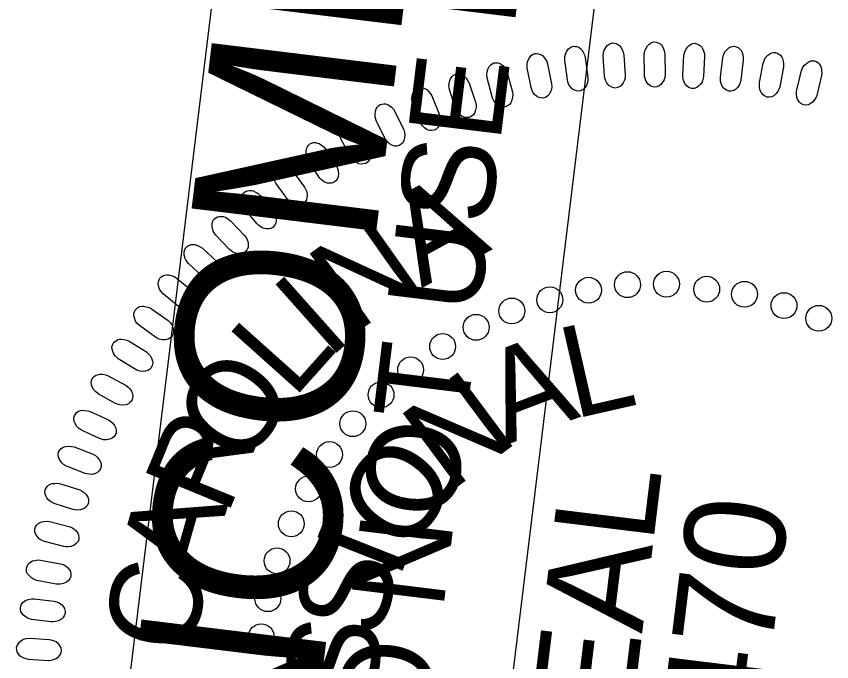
# Model space of a CAD drawing. Extents: x 480792 to 482083, y 490046 to 491850.
# Drawn here: x 481060.3 to 481110.8, y 491670.1 to 491710 of the extents above; entities that cross this region are included whole.
import ezdxf

# ---------------------------------------------------------------- set-up
doc = ezdxf.new("R2010")
doc.units = 0
doc.layers.add('Sheet PE Seal Cell', color=7, linetype='Continuous')
doc.layers.add('Sheet Sticker Incomplete CELL', color=7, linetype='Continuous')

msp = doc.modelspace()

# ---------------------------------------------------------------- linework, layer by layer
at = {"layer": 'Sheet PE Seal Cell'}
for points in [[(481096.688, 491706.346), (481096.606, 491707.57), (481096.629, 491707.792), (481096.671, 491707.935), (481096.772, 491708.111), (481096.862, 491708.227), (481096.969, 491708.315), (481097.07, 491708.361), (481097.181, 491708.389), (481097.294, 491708.376), (481097.416, 491708.353), (481097.523, 491708.301), (481097.634, 491708.209), (481097.7, 491708.133), (481097.777, 491707.988), (481097.848, 491707.813), (481097.881, 491707.656), (481097.973, 491706.402), (481097.961, 491706.231), (481097.926, 491706.089), (481097.847, 491705.924), (481097.744, 491705.777), (481097.653, 491705.691), (481097.5, 491705.621), (481097.352, 491705.591), (481097.201, 491705.621), (481097.093, 491705.664), (481096.959, 491705.755), (481096.829, 491705.916), (481096.749, 491706.091), (481096.711, 491706.218)], [(481099.157, 491706.446), (481099.153, 491707.672), (481099.189, 491707.892), (481099.241, 491708.032), (481099.352, 491708.202), (481099.449, 491708.312), (481099.561, 491708.392), (481099.665, 491708.433), (481099.777, 491708.453), (481099.889, 491708.433), (481100.009, 491708.404), (481100.115, 491708.345), (481100.219, 491708.245), (481100.279, 491708.166), (481100.347, 491708.016), (481100.408, 491707.837), (481100.431, 491707.677), (481100.443, 491706.421), (481100.421, 491706.251), (481100.377, 491706.111), (481100.288, 491705.952), (481100.176, 491705.811), (481100.079, 491705.731), (481099.923, 491705.67), (481099.773, 491705.65), (481099.623, 491705.69), (481099.519, 491705.739), (481099.391, 491705.838), (481099.271, 491706.007), (481099.203, 491706.187), (481099.173, 491706.317)], [(481101.534, 491706.401), (481101.607, 491707.625), (481101.657, 491707.842), (481101.717, 491707.978), (481101.839, 491708.141), (481101.942, 491708.245), (481102.06, 491708.318), (481102.166, 491708.351), (481102.279, 491708.365), (481102.39, 491708.338), (481102.508, 491708.301), (481102.608, 491708.236), (481102.707, 491708.13), (481102.762, 491708.046), (481102.821, 491707.893), (481102.87, 491707.71), (481102.883, 491707.55), (481102.816, 491706.295), (481102.783, 491706.127), (481102.73, 491705.99), (481102.631, 491705.836), (481102.511, 491705.704), (481102.41, 491705.63), (481102.249, 491705.579), (481102.099, 491705.568), (481101.952, 491705.617), (481101.85, 491705.673), (481101.729, 491705.78), (481101.62, 491705.956), (481101.563, 491706.139), (481101.541, 491706.27)], [(481092.141, 491705.638), (481091.906, 491706.842), (481091.901, 491707.065), (481091.926, 491707.212), (481092.004, 491707.399), (481092.078, 491707.526), (481092.173, 491707.626), (481092.267, 491707.685), (481092.374, 491707.725), (481092.488, 491707.727), (481092.611, 491707.721), (481092.725, 491707.682), (481092.847, 491707.604), (481092.921, 491707.538), (481093.016, 491707.403), (481093.109, 491707.239), (481093.162, 491707.086), (481093.409, 491705.854), (481093.419, 491705.684), (481093.401, 491705.538), (481093.344, 491705.365), (481093.261, 491705.206), (481093.18, 491705.109), (481093.038, 491705.02), (481092.895, 491704.972), (481092.74, 491704.983), (481092.629, 491705.012), (481092.484, 491705.085), (481092.335, 491705.228), (481092.234, 491705.392), (481092.18, 491705.514)], [(481094.388, 491706.114), (481094.23, 491707.33), (481094.239, 491707.552), (481094.272, 491707.698), (481094.362, 491707.881), (481094.444, 491708.002), (481094.545, 491708.095), (481094.643, 491708.148), (481094.752, 491708.182), (481094.866, 491708.178), (481094.989, 491708.163), (481095.099, 491708.118), (481095.216, 491708.032), (481095.286, 491707.961), (481095.372, 491707.821), (481095.455, 491707.65), (481095.498, 491707.495), (481095.667, 491706.25), (481095.667, 491706.079), (481095.64, 491705.935), (481095.572, 491705.765), (481095.479, 491705.612), (481095.393, 491705.52), (481095.245, 491705.441), (481095.099, 491705.402), (481094.946, 491705.422), (481094.836, 491705.458), (481094.697, 491705.54), (481094.556, 491705.693), (481094.466, 491705.862), (481094.42, 491705.987)], [(481103.865, 491706.266), (481104.015, 491707.484), (481104.078, 491707.697), (481104.147, 491707.829), (481104.279, 491707.984), (481104.389, 491708.082), (481104.51, 491708.147), (481104.618, 491708.173), (481104.732, 491708.179), (481104.841, 491708.146), (481104.956, 491708.102), (481105.053, 491708.03), (481105.144, 491707.918), (481105.194, 491707.832), (481105.243, 491707.675), (481105.28, 491707.49), (481105.283, 491707.329), (481105.138, 491706.08), (481105.095, 491705.915), (481105.033, 491705.782), (481104.925, 491705.634), (481104.797, 491705.509), (481104.691, 491705.442), (481104.527, 491705.401), (481104.377, 491705.4), (481104.233, 491705.458), (481104.136, 491705.52), (481104.021, 491705.634), (481103.924, 491705.817), (481103.878, 491706.004), (481103.864, 491706.136)], [(481106.284, 491705.938), (481106.509, 491707.144), (481106.586, 491707.352), (481106.663, 491707.48), (481106.805, 491707.626), (481106.92, 491707.716), (481107.045, 491707.774), (481107.155, 491707.794), (481107.27, 491707.793), (481107.375, 491707.752), (481107.488, 491707.701), (481107.58, 491707.623), (481107.664, 491707.506), (481107.708, 491707.417), (481107.747, 491707.257), (481107.773, 491707.069), (481107.766, 491706.908), (481107.542, 491705.672), (481107.489, 491705.51), (481107.419, 491705.381), (481107.302, 491705.24), (481107.166, 491705.124), (481107.056, 491705.063), (481106.89, 491705.033), (481106.739, 491705.041), (481106.6, 491705.108), (481106.506, 491705.176), (481106.4, 491705.297), (481106.313, 491705.485), (481106.28, 491705.675), (481106.275, 491705.807)], [(481108.586, 491705.488), (481108.887, 491706.678), (481108.977, 491706.881), (481109.061, 491707.004), (481109.212, 491707.142), (481109.333, 491707.224), (481109.461, 491707.273), (481109.572, 491707.287), (481109.686, 491707.278), (481109.79, 491707.232), (481109.899, 491707.173), (481109.985, 491707.09), (481110.062, 491706.967), (481110.101, 491706.876), (481110.129, 491706.714), (481110.143, 491706.525), (481110.126, 491706.365), (481109.825, 491705.145), (481109.762, 491704.985), (481109.684, 491704.861), (481109.558, 491704.729), (481109.415, 491704.621), (481109.302, 491704.567), (481109.135, 491704.548), (481108.985, 491704.565), (481108.85, 491704.641), (481108.76, 491704.714), (481108.661, 491704.842), (481108.588, 491705.036), (481108.566, 491705.227), (481108.569, 491705.359)], [(481089.738, 491705.051), (481089.428, 491706.238), (481089.409, 491706.459), (481089.424, 491706.608), (481089.49, 491706.8), (481089.557, 491706.931), (481089.645, 491707.036), (481089.736, 491707.101), (481089.84, 491707.149), (481089.953, 491707.157), (481090.076, 491707.159), (481090.192, 491707.128), (481090.319, 491707.057), (481090.397, 491706.996), (481090.5, 491706.868), (481090.603, 491706.709), (481090.665, 491706.56), (481090.989, 491705.346), (481091.011, 491705.177), (481091.002, 491705.03), (481090.956, 491704.853), (481090.883, 491704.69), (481090.809, 491704.588), (481090.672, 491704.49), (481090.532, 491704.433), (481090.378, 491704.434), (481090.264, 491704.456), (481090.115, 491704.52), (481089.957, 491704.655), (481089.846, 491704.811), (481089.785, 491704.929)], [(481087.474, 491704.341), (481087.09, 491705.506), (481087.057, 491705.726), (481087.063, 491705.875), (481087.117, 491706.071), (481087.175, 491706.205), (481087.256, 491706.317), (481087.343, 491706.387), (481087.444, 491706.441), (481087.556, 491706.457), (481087.679, 491706.466), (481087.797, 491706.442), (481087.928, 491706.38), (481088.01, 491706.323), (481088.121, 491706.201), (481088.233, 491706.05), (481088.304, 491705.905), (481088.704, 491704.714), (481088.736, 491704.546), (481088.737, 491704.399), (481088.702, 491704.22), (481088.639, 491704.052), (481088.572, 491703.946), (481088.441, 491703.84), (481088.305, 491703.774), (481088.151, 491703.765), (481088.036, 491703.78), (481087.884, 491703.835), (481087.717, 491703.959), (481087.597, 491704.108), (481087.529, 491704.222)], [(481085.272, 491703.494), (481084.816, 491704.633), (481084.77, 491704.85), (481084.765, 491704.999), (481084.806, 491705.198), (481084.856, 491705.336), (481084.931, 491705.452), (481085.014, 491705.528), (481085.11, 491705.588), (481085.221, 491705.611), (481085.343, 491705.628), (481085.463, 491705.612), (481085.597, 491705.558), (481085.682, 491705.506), (481085.8, 491705.392), (481085.922, 491705.247), (481086.003, 491705.108), (481086.477, 491703.944), (481086.519, 491703.778), (481086.529, 491703.631), (481086.505, 491703.45), (481086.453, 491703.28), (481086.392, 491703.169), (481086.269, 491703.055), (481086.137, 491702.981), (481085.984, 491702.962), (481085.868, 491702.969), (481085.713, 491703.015), (481085.539, 491703.128), (481085.41, 491703.27), (481085.334, 491703.379)], [(481083.085, 491702.491), (481082.558, 491703.598), (481082.497, 491703.813), (481082.484, 491703.961), (481082.513, 491704.163), (481082.554, 491704.304), (481082.62, 491704.424), (481082.698, 491704.505), (481082.791, 491704.571), (481082.9, 491704.601), (481083.022, 491704.625), (481083.141, 491704.616), (481083.279, 491704.571), (481083.367, 491704.525), (481083.493, 491704.418), (481083.623, 491704.282), (481083.712, 491704.148), (481084.258, 491703.016), (481084.311, 491702.853), (481084.33, 491702.708), (481084.317, 491702.525), (481084.276, 491702.35), (481084.223, 491702.237), (481084.107, 491702.115), (481083.98, 491702.033), (481083.828, 491702.005), (481083.712, 491702.005), (481083.554, 491702.041), (481083.374, 491702.142), (481083.236, 491702.276), (481083.153, 491702.38)], [(481080.983, 491701.336), (481080.388, 491702.409), (481080.314, 491702.619), (481080.292, 491702.766), (481080.308, 491702.97), (481080.34, 491703.112), (481080.399, 491703.236), (481080.471, 491703.322), (481080.56, 491703.394), (481080.668, 491703.431), (481080.786, 491703.463), (481080.907, 491703.461), (481081.047, 491703.425), (481081.138, 491703.384), (481081.269, 491703.285), (481081.409, 491703.158), (481081.506, 491703.029), (481082.122, 491701.934), (481082.184, 491701.775), (481082.213, 491701.63), (481082.212, 491701.448), (481082.181, 491701.271), (481082.135, 491701.154), (481082.027, 491701.026), (481081.906, 491700.936), (481081.756, 491700.898), (481081.64, 491700.891), (481081.48, 491700.917), (481081.294, 491701.007), (481081.148, 491701.131), (481081.059, 491701.231)], [(481078.997, 491700.108), (481078.335, 491701.141), (481078.249, 491701.346), (481078.217, 491701.492), (481078.221, 491701.695), (481078.243, 491701.84), (481078.295, 491701.968), (481078.361, 491702.058), (481078.445, 491702.135), (481078.55, 491702.179), (481078.667, 491702.218), (481078.788, 491702.224), (481078.93, 491702.196), (481079.023, 491702.161), (481079.16, 491702.071), (481079.307, 491701.952), (481079.412, 491701.83), (481080.096, 491700.776), (481080.168, 491700.621), (481080.206, 491700.479), (481080.216, 491700.296), (481080.197, 491700.118), (481080.158, 491699.998), (481080.059, 491699.863), (481079.943, 491699.766), (481079.796, 491699.719), (481079.681, 491699.705), (481079.52, 491699.72), (481079.328, 491699.799), (481079.174, 491699.914), (481079.079, 491700.007)], [(481077.068, 491698.719), (481076.343, 491699.709), (481076.244, 491699.908), (481076.203, 491700.052), (481076.193, 491700.255), (481076.207, 491700.4), (481076.25, 491700.531), (481076.311, 491700.626), (481076.39, 491700.708), (481076.492, 491700.758), (481076.607, 491700.805), (481076.726, 491700.818), (481076.87, 491700.8), (481076.965, 491700.77), (481077.108, 491700.689), (481077.262, 491700.58), (481077.375, 491700.465), (481078.123, 491699.455), (481078.205, 491699.305), (481078.251, 491699.166), (481078.273, 491698.984), (481078.265, 491698.805), (481078.234, 491698.683), (481078.143, 491698.542), (481078.034, 491698.438), (481077.89, 491698.381), (481077.776, 491698.36), (481077.614, 491698.365), (481077.418, 491698.432), (481077.257, 491698.537), (481077.157, 491698.624)], [(481075.176, 491697.193), (481074.39, 491698.136), (481074.278, 491698.328), (481074.229, 491698.469), (481074.206, 491698.671), (481074.211, 491698.817), (481074.246, 491698.95), (481074.3, 491699.048), (481074.374, 491699.135), (481074.473, 491699.192), (481074.584, 491699.245), (481074.702, 491699.266), (481074.847, 491699.257), (481074.944, 491699.234), (481075.091, 491699.162), (481075.252, 491699.062), (481075.372, 491698.954), (481076.182, 491697.994), (481076.273, 491697.849), (481076.328, 491697.713), (481076.361, 491697.533), (481076.365, 491697.355), (481076.341, 491697.23), (481076.259, 491697.084), (481076.157, 491696.973), (481076.017, 491696.908), (481075.904, 491696.879), (481075.743, 491696.875), (481075.542, 491696.928), (481075.376, 491697.023), (481075.27, 491697.104)], [(481073.458, 491695.618), (481072.615, 491696.509), (481072.491, 491696.694), (481072.433, 491696.831), (481072.398, 491697.032), (481072.393, 491697.178), (481072.42, 491697.313), (481072.468, 491697.414), (481072.537, 491697.506), (481072.631, 491697.568), (481072.739, 491697.629), (481072.856, 491697.657), (481073, 491697.657), (481073.099, 491697.64), (481073.25, 491697.577), (481073.417, 491697.488), (481073.543, 491697.388), (481074.412, 491696.48), (481074.513, 491696.342), (481074.576, 491696.209), (481074.62, 491696.032), (481074.635, 491695.853), (481074.62, 491695.728), (481074.547, 491695.577), (481074.451, 491695.46), (481074.315, 491695.386), (481074.205, 491695.35), (481074.044, 491695.336), (481073.841, 491695.377), (481073.668, 491695.461), (481073.558, 491695.535)], [(481071.822, 491693.909), (481070.925, 491694.746), (481070.79, 491694.923), (481070.723, 491695.056), (481070.676, 491695.254), (481070.662, 491695.399), (481070.679, 491695.536), (481070.722, 491695.64), (481070.784, 491695.736), (481070.875, 491695.804), (481070.978, 491695.871), (481071.093, 491695.907), (481071.238, 491695.915), (481071.337, 491695.905), (481071.492, 491695.852), (481071.664, 491695.773), (481071.796, 491695.681), (481072.721, 491694.83), (481072.829, 491694.697), (481072.901, 491694.569), (481072.957, 491694.395), (481072.983, 491694.218), (481072.974, 491694.092), (481072.911, 491693.937), (481072.823, 491693.814), (481072.693, 491693.731), (481072.585, 491693.689), (481072.425, 491693.664), (481072.22, 491693.692), (481072.042, 491693.766), (481071.927, 491693.832)], [(481070.316, 491692.079), (481069.368, 491692.857), (481069.222, 491693.025), (481069.148, 491693.154), (481069.087, 491693.348), (481069.064, 491693.493), (481069.074, 491693.63), (481069.109, 491693.736), (481069.165, 491693.836), (481069.252, 491693.91), (481069.351, 491693.983), (481069.463, 491694.026), (481069.607, 491694.044), (481069.706, 491694.039), (481069.865, 491693.997), (481070.042, 491693.929), (481070.179, 491693.845), (481071.155, 491693.053), (481071.272, 491692.928), (481071.351, 491692.805), (481071.418, 491692.635), (481071.455, 491692.46), (481071.455, 491692.334), (481071.401, 491692.174), (481071.322, 491692.046), (481071.196, 491691.956), (481071.091, 491691.907), (481070.933, 491691.871), (481070.727, 491691.887), (481070.545, 491691.949), (481070.426, 491692.008)], [(481068.89, 491690.18), (481067.895, 491690.896), (481067.739, 491691.055), (481067.656, 491691.179), (481067.585, 491691.369), (481067.552, 491691.512), (481067.553, 491691.65), (481067.582, 491691.758), (481067.631, 491691.861), (481067.713, 491691.94), (481067.807, 491692.019), (481067.917, 491692.07), (481068.059, 491692.096), (481068.159, 491692.098), (481068.319, 491692.066), (481068.5, 491692.008), (481068.643, 491691.934), (481069.666, 491691.205), (481069.791, 491691.088), (481069.878, 491690.97), (481069.955, 491690.804), (481070.003, 491690.631), (481070.011, 491690.505), (481069.967, 491690.343), (481069.896, 491690.21), (481069.777, 491690.112), (481069.674, 491690.056), (481069.519, 491690.012), (481069.312, 491690.014), (481069.127, 491690.064), (481069.004, 491690.116)], [(481067.625, 491688.194), (481066.587, 491688.848), (481066.421, 491688.996), (481066.331, 491689.115), (481066.247, 491689.3), (481066.206, 491689.44), (481066.198, 491689.578), (481066.22, 491689.688), (481066.263, 491689.793), (481066.34, 491689.877), (481066.428, 491689.963), (481066.535, 491690.02), (481066.675, 491690.055), (481066.774, 491690.063), (481066.937, 491690.04), (481067.121, 491689.995), (481067.268, 491689.93), (481068.335, 491689.266), (481068.467, 491689.157), (481068.561, 491689.045), (481068.649, 491688.884), (481068.707, 491688.714), (481068.723, 491688.59), (481068.69, 491688.425), (481068.627, 491688.288), (481068.514, 491688.183), (481068.416, 491688.121), (481068.263, 491688.066), (481068.057, 491688.055), (481067.868, 491688.094), (481067.743, 491688.138)], [(481066.426, 491686.083), (481065.349, 491686.669), (481065.174, 491686.808), (481065.076, 491686.92), (481064.981, 491687.1), (481064.931, 491687.238), (481064.915, 491687.374), (481064.93, 491687.485), (481064.966, 491687.593), (481065.037, 491687.682), (481065.121, 491687.773), (481065.224, 491687.836), (481065.361, 491687.88), (481065.46, 491687.895), (481065.623, 491687.882), (481065.81, 491687.849), (481065.96, 491687.792), (481067.068, 491687.198), (481067.206, 491687.096), (481067.307, 491686.99), (481067.404, 491686.835), (481067.473, 491686.67), (481067.497, 491686.547), (481067.474, 491686.38), (481067.42, 491686.239), (481067.313, 491686.127), (481067.22, 491686.059), (481067.071, 491685.995), (481066.865, 491685.972), (481066.675, 491685.998), (481066.547, 491686.034)], [(481065.42, 491683.905), (481064.308, 491684.423), (481064.124, 491684.55), (481064.021, 491684.656), (481063.914, 491684.83), (481063.856, 491684.964), (481063.83, 491685.099), (481063.839, 491685.211), (481063.868, 491685.321), (481063.933, 491685.414), (481064.011, 491685.51), (481064.11, 491685.58), (481064.244, 491685.632), (481064.342, 491685.653), (481064.506, 491685.651), (481064.694, 491685.629), (481064.848, 491685.582), (481065.99, 491685.058), (481066.135, 491684.967), (481066.242, 491684.866), (481066.349, 491684.718), (481066.428, 491684.557), (481066.459, 491684.436), (481066.447, 491684.268), (481066.401, 491684.124), (481066.303, 491684.005), (481066.213, 491683.932), (481066.069, 491683.858), (481065.865, 491683.822), (481065.674, 491683.836), (481065.544, 491683.864)], [(481064.53, 491681.747), (481063.387, 491682.194), (481063.197, 491682.309), (481063.086, 491682.409), (481062.968, 491682.575), (481062.902, 491682.705), (481062.869, 491682.839), (481062.87, 491682.951), (481062.892, 491683.063), (481062.951, 491683.16), (481063.023, 491683.261), (481063.116, 491683.336), (481063.247, 491683.397), (481063.343, 491683.424), (481063.508, 491683.432), (481063.697, 491683.422), (481063.854, 491683.385), (481065.026, 491682.934), (481065.176, 491682.85), (481065.289, 491682.758), (481065.405, 491682.616), (481065.495, 491682.461), (481065.534, 491682.342), (481065.532, 491682.174), (481065.496, 491682.027), (481065.404, 491681.903), (481065.32, 491681.823), (481065.181, 491681.741), (481064.979, 491681.691), (481064.787, 491681.695), (481064.656, 491681.714)], [(481063.78, 491679.516), (481062.612, 491679.891), (481062.414, 491679.994), (481062.298, 491680.086), (481062.17, 491680.245), (481062.096, 491680.371), (481062.054, 491680.502), (481062.048, 491680.614), (481062.063, 491680.727), (481062.116, 491680.827), (481062.181, 491680.932), (481062.27, 491681.013), (481062.397, 491681.083), (481062.491, 491681.115), (481062.654, 491681.133), (481062.844, 491681.136), (481063.003, 491681.108), (481064.201, 491680.732), (481064.355, 491680.658), (481064.475, 491680.573), (481064.599, 491680.439), (481064.698, 491680.289), (481064.745, 491680.173), (481064.753, 491680.005), (481064.727, 491679.857), (481064.643, 491679.726), (481064.564, 491679.642), (481064.43, 491679.552), (481064.232, 491679.489), (481064.041, 491679.48), (481063.908, 491679.491)], [(481063.212, 491677.229), (481062.023, 491677.53), (481061.819, 491677.62), (481061.697, 491677.705), (481061.56, 491677.855), (481061.477, 491677.976), (481061.427, 491678.104), (481061.414, 491678.215), (481061.422, 491678.329), (481061.469, 491678.433), (481061.527, 491678.541), (481061.611, 491678.628), (481061.734, 491678.705), (481061.825, 491678.744), (481061.987, 491678.773), (481062.176, 491678.786), (481062.336, 491678.769), (481063.556, 491678.468), (481063.715, 491678.405), (481063.839, 491678.328), (481063.972, 491678.201), (481064.08, 491678.058), (481064.133, 491677.945), (481064.153, 491677.778), (481064.136, 491677.628), (481064.06, 491677.493), (481063.987, 491677.404), (481063.859, 491677.304), (481063.665, 491677.23), (481063.474, 491677.209), (481063.341, 491677.212)], [(481062.752, 491674.905), (481061.546, 491675.131), (481061.337, 491675.207), (481061.209, 491675.285), (481061.063, 491675.426), (481060.973, 491675.542), (481060.915, 491675.667), (481060.896, 491675.777), (481060.897, 491675.891), (481060.937, 491675.997), (481060.988, 491676.109), (481061.066, 491676.201), (481061.183, 491676.286), (481061.273, 491676.33), (481061.432, 491676.369), (481061.619, 491676.394), (481061.78, 491676.388), (481063.017, 491676.163), (481063.18, 491676.111), (481063.309, 491676.041), (481063.449, 491675.923), (481063.565, 491675.788), (481063.627, 491675.677), (481063.656, 491675.512), (481063.649, 491675.361), (481063.582, 491675.222), (481063.513, 491675.128), (481063.392, 491675.021), (481063.204, 491674.935), (481063.015, 491674.902), (481062.881, 491674.896)], [(481062.439, 491672.567), (481061.222, 491672.716), (481061.009, 491672.78), (481060.876, 491672.849), (481060.722, 491672.981), (481060.624, 491673.091), (481060.559, 491673.211), (481060.532, 491673.32), (481060.526, 491673.434), (481060.559, 491673.543), (481060.603, 491673.658), (481060.675, 491673.754), (481060.787, 491673.846), (481060.874, 491673.896), (481061.031, 491673.944), (481061.216, 491673.982), (481061.377, 491673.985), (481062.625, 491673.839), (481062.791, 491673.797), (481062.924, 491673.735), (481063.071, 491673.627), (481063.197, 491673.498), (481063.264, 491673.392), (481063.304, 491673.229), (481063.305, 491673.078), (481063.248, 491672.935), (481063.186, 491672.837), (481063.072, 491672.723), (481062.888, 491672.625), (481062.702, 491672.58), (481062.57, 491672.566)], [(481062.313, 491671.459), (481061.088, 491671.531), (481060.867, 491671.506), (481060.725, 491671.463), (481060.549, 491671.361), (481060.434, 491671.27), (481060.347, 491671.163), (481060.301, 491671.061), (481060.275, 491670.95), (481060.288, 491670.837), (481060.311, 491670.716), (481060.364, 491670.608), (481060.458, 491670.497), (481060.534, 491670.433), (481060.679, 491670.357), (481060.855, 491670.287), (481061.013, 491670.255), (481062.267, 491670.174), (481062.437, 491670.186), (481062.579, 491670.223), (481062.744, 491670.302), (481062.89, 491670.406), (481062.976, 491670.498), (481063.045, 491670.652), (481063.074, 491670.8), (481063.042, 491670.952), (481062.998, 491671.059), (481062.906, 491671.191), (481062.744, 491671.321), (481062.569, 491671.398), (481062.441, 491671.436)]]:
    msp.add_lwpolyline(points, close=True, dxfattribs=at)
for centre in [(481098.113, 491693.429), (481100.525, 491693.455), (481095.703, 491693.083), (481103.016, 491693.15), (481105.359, 491692.834), (481093.303, 491692.494), (481090.953, 491691.802), (481107.801, 491692.133), (481109.953, 491691.348), (481088.742, 491690.789), (481086.669, 491689.599), (481084.687, 491688.157), (481082.853, 491686.617), (481081.108, 491684.825), (481079.67, 491682.915), (481078.366, 491680.789), (481077.299, 491678.633), (481076.416, 491676.335), (481075.849, 491673.997), (481075.44, 491671.641)]:
    msp.add_circle(centre, 0.801, dxfattribs=at)
at = {"layer": 'Sheet Sticker Incomplete CELL'}
msp.add_lwpolyline([(481088.269, 491646.965), (481064.942, 491649.814), (481082.764, 491795.73), (481106.09, 491792.881)], close=True, dxfattribs=at)

# ---------------------------------------------------------------- texts
at = {"layer": 'Sheet PE Seal Cell'}
for s, height, rotation, p in [('A', 5.669, 28.7093, (481085.357, 491693.203)), ('N', 5.669, 35.1987, (481081.202, 491690.366)), ('I', 5.669, 41.688, (481079.574, 491688.746)), ('L', 5.669, 48.1774, (481077.408, 491686.298)), ('L', 5.669, 12.8674, (481094.779, 491685.109)), ('A', 5.669, 20.8072, (481090.556, 491683.486)), ('O', 5.669, 54.6668, (481074.321, 491681.907)), ('N', 5.669, 36.6868, (481087.093, 491680.547)), ('R', 5.669, 67.6455, (481073.314, 491679.053)), ('O', 5.669, 52.5664, (481084.283, 491676.546)), ('SEAL', 6.2363, 83.0179, (481097.66, 491660.759)), ('29470', 6.2363, 83.0179, (481105.319, 491656.83)), ('A', 5.669, 74.1348, (481072.016, 491674.974)), ('I', 5.669, 68.4459, (481083.931, 491675.074)), ('S', 5.669, 76.3857, (481082.843, 491671.378)), ('C', 5.669, 80.6242, (481071.254, 491670.457)), ('S', 5.669, 84.3255, (481082.475, 491667.534))]:
    msp.add_text(s, height=height, rotation=rotation, dxfattribs=at).set_placement(p)
at = {"layer": 'Sheet Sticker Incomplete CELL'}
for s, height, p in [('INCOMPLETE PLANS', 11.52, (481077.74, 491657.268)), ('DO NOT USE FOR R/W ACQUISITION', 5.76, (481085.033, 491659.651))]:
    msp.add_text(s, height=height, rotation=83.0365, dxfattribs=at).set_placement(p)

doc.saveas('drawing.dxf')
